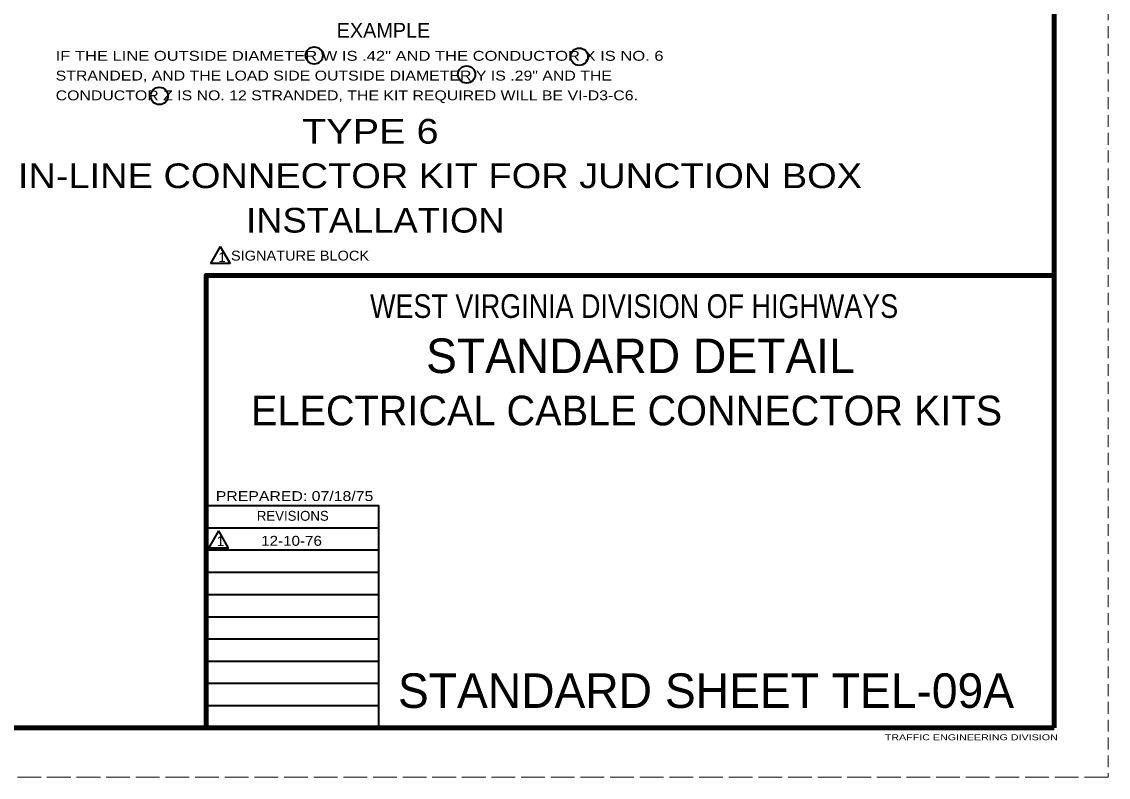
# Model space of a CAD drawing. Extents: x -1 to 679, y 0 to 440.
# Drawn here: x 458.8 to 678.7, y -0.1 to 152.8 of the extents above; entities that cross this region are included whole.
import ezdxf
from ezdxf.enums import TextEntityAlignment as Align

# ---------------------------------------------------------------- set-up
doc = ezdxf.new("R2010")
doc.units = 0
doc.header["$LTSCALE"] = 0.8
doc.linetypes.add('LONG_DASHED', pattern=[7.5, 6, -1.5])
doc.linetypes.add('MEDIUM_DASHED', pattern=[4.5, 3, -1.5])
doc.layers.add('1', color=7, linetype='Continuous', lineweight=53)
doc.layers.add('61', color=7, linetype='Continuous', lineweight=35)

msp = doc.modelspace()

# ---------------------------------------------------------------- linework, layer by layer
at = {"layer": '1', "linetype": 'MEDIUM_DASHED', "lineweight": 13}
msp.add_line((678.735, 439.9088), (678.715, -0.1112), dxfattribs=at)
at = {"layer": '1', "lineweight": 35}
for p, q in [((499.0002, 107.3101), (497.0002, 103.846)), ((499.0002, 107.3101), (501.0002, 103.846)), ((501.0002, 103.846), (497.0002, 103.846)), ((531.115, 50.3088), (496.135, 50.3088)), ((498.6195, 49.7329), (496.6195, 46.2688)), ((531.115, 45.8088), (496.135, 45.8088)), ((531.115, 41.3088), (496.135, 41.3088)), ((531.115, 36.7888), (496.135, 36.7888)), ((531.115, 32.3088), (496.135, 32.3088)), ((531.115, 27.8288), (496.135, 27.8288)), ((531.115, 23.3288), (496.135, 23.3288)), ((531.115, 18.8288), (496.135, 18.8288)), ((531.115, 14.3088), (496.135, 14.3088))]:
    msp.add_line(p, q, dxfattribs=at)
at = {"layer": '1', "lineweight": 158}
msp.add_lwpolyline([(496.115, 9.8688), (496.115, 101.4488), (667.775, 101.4488)], dxfattribs=at)
at = {"layer": '1', "lineweight": 35}
for points in [[(531.115, 9.8288), (531.115, 54.7888), (496.135, 54.7888)], [(498.6195, 49.7329), (500.6195, 46.2688), (496.6195, 46.2688)]]:
    msp.add_lwpolyline(points, dxfattribs=at)
for centre in [(518.0023, 145.9683), (571.6589, 145.7204), (548.8579, 142.1257), (486.651, 137.7871)]:
    msp.add_circle(centre, 1.75, dxfattribs=at)
at = {"layer": '61', "lineweight": 158}
for p, q in [((667.755, 429.9088), (667.775, 9.8688)), ((667.775, 9.8688), (28.715, 9.8888))]:
    msp.add_line(p, q, dxfattribs=at)
at = {"layer": '61', "linetype": 'LONG_DASHED', "lineweight": 13}
msp.add_line((678.715, -0.1112), (-1.345, -0.1312), dxfattribs=at)

# ---------------------------------------------------------------- texts
at = {"layer": '1'}
for s, height, p in [('EXAMPLE', 3, (522.5507, 149.5705)), ('1', 2, (498.6119, 104.1359)), ('ELECTRICAL CABLE CONNECTOR KITS', 6, (505.219, 71.1041)), ('REVISIONS', 1.998, (506.395, 51.7888)), ('1', 2, (498.2981, 46.6804)), ('STANDARD SHEET TEL-09A', 6.993, (534.955, 13.9088))]:
    msp.add_text(s, height=height, dxfattribs=at).set_placement(p)
for s, height, width, p in [('IF THE LINE OUTSIDE DIAMETER W IS .42" AND THE CONDUCTOR X IS NO. 6', 2, 1.25, (465.673, 144.8997)), ('STRANDED, AND THE LOAD SIDE OUTSIDE DIAMETER Y IS .29" AND THE', 2, 1.2, (465.673, 140.8997)), ('CONDUCTOR Z IS NO. 12 STRANDED, THE KIT REQUIRED WILL BE VI-D3-C6.', 2, 1.2, (465.673, 136.8997)), ('SIGNATURE BLOCK', 2, 1.1, (501.158, 104.4583)), ('PREPARED: 07/18/75', 1.998, 1.2, (498.075, 55.7888)), ('TRAFFIC ENGINEERING DIVISION', 1.2, 1.35, (633.495, 7.3688))]:
    msp.add_text(s, height=height, dxfattribs=dict(at, width=width)).set_placement(p)
for s, height, width, p in [('TYPE 6', 5, 1.2, (529.3566, 128.1238)), ('FUSED IN-LINE CONNECTOR KIT FOR JUNCTION BOX', 5, 1.15, (529.3566, 119.1238)), (' INSTALLATION', 5, 1.1, (529.3565, 110.1238)), ('WEST VIRGINIA DIVISION OF HIGHWAYS', 4.795, 0.85, (582.7633, 92.8488)), ('12-10-76', 2, 1.15, (513.415, 46.7288))]:
    msp.add_text(s, height=height, dxfattribs=dict(at, width=width)).set_placement(p, align=Align.CENTER)
msp.add_text('STANDARD DETAIL', height=6.993, dxfattribs=at).set_placement((584.032, 81.6888), align=Align.CENTER)

doc.saveas('drawing.dxf')
